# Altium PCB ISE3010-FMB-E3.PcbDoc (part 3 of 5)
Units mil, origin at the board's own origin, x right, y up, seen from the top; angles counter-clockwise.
Board outline 7874.02 x 2362.2 mil, 4 copper layers (Top Layer, MidLayer1, MidLayer2, Bottom Layer), stack 55.6 mil thick; 507 components, 331 nets, 1707 pads, 610 vias.
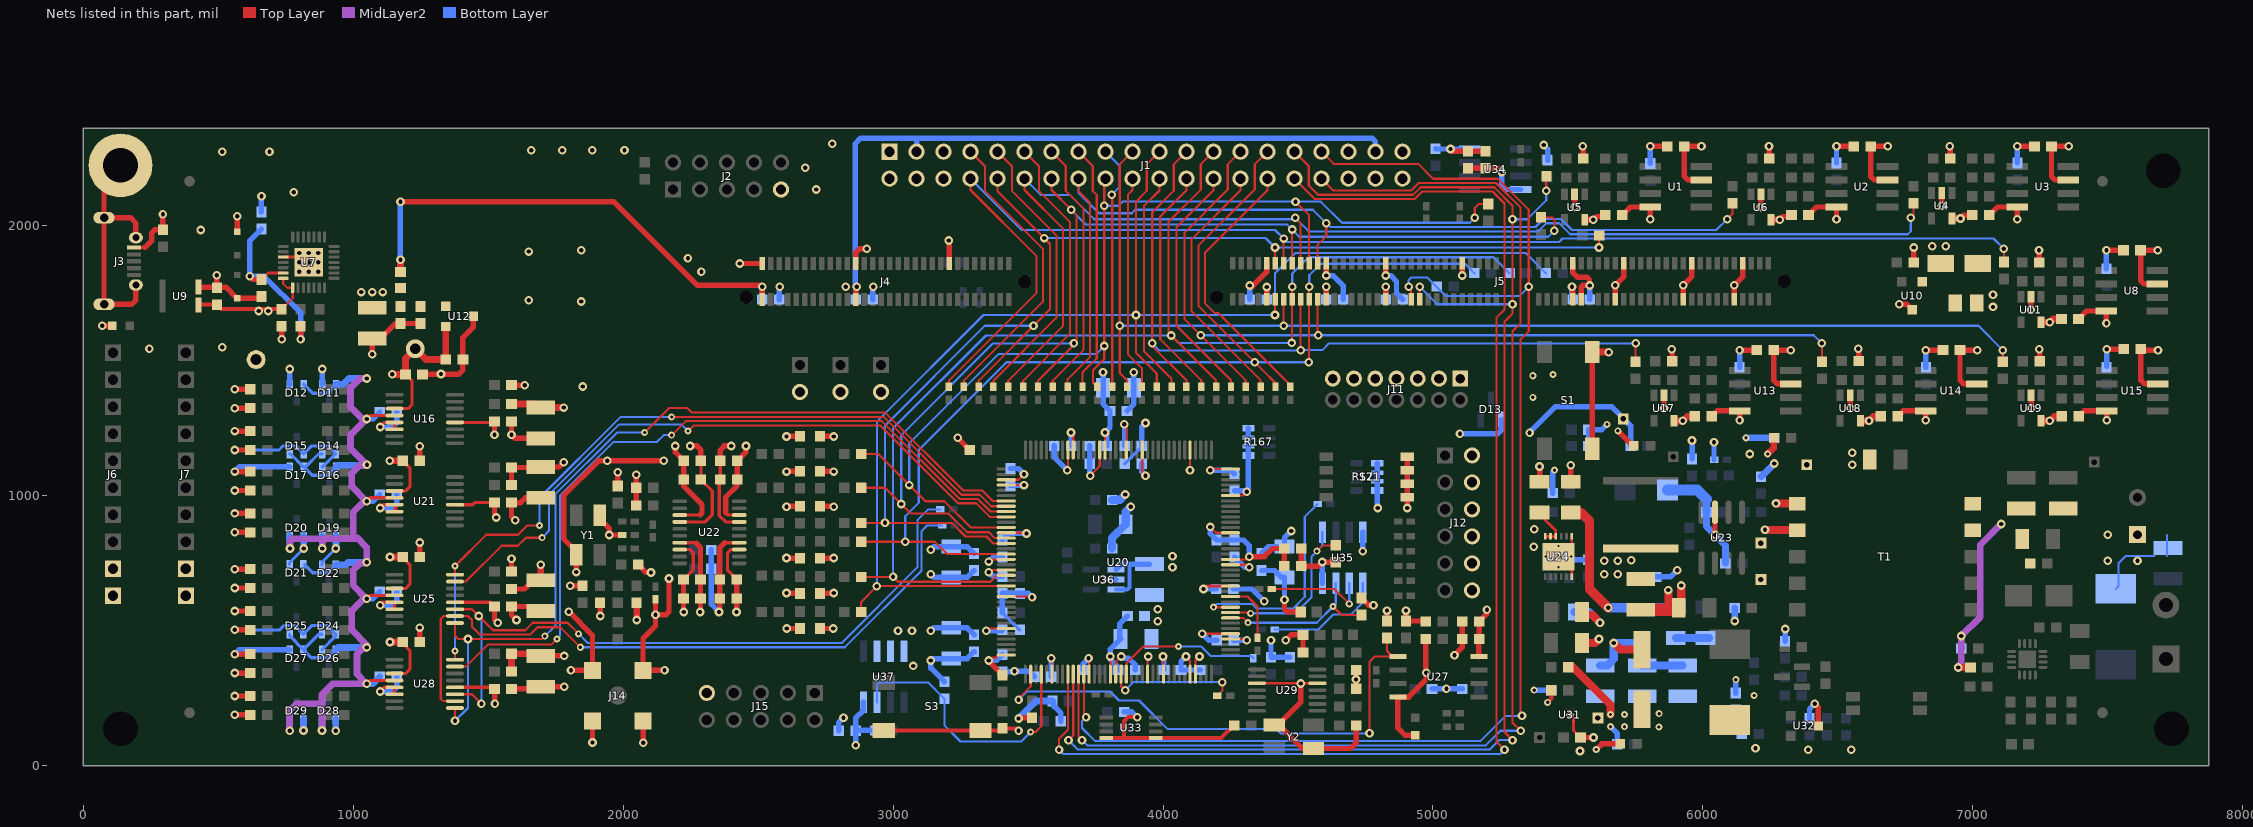
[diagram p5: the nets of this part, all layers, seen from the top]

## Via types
v1: diameter 32, hole 16, Top Layer to Bottom Layer, tented both sides, 495 vias
v2: diameter 26, hole 12, Top Layer to Bottom Layer, tented both sides, 104 vias
v3: diameter 20, hole 8, Top Layer to Bottom Layer, tented both sides, 10 vias
v4: diameter 30, hole 16, Top Layer to Bottom Layer, tented both sides, 1 vias

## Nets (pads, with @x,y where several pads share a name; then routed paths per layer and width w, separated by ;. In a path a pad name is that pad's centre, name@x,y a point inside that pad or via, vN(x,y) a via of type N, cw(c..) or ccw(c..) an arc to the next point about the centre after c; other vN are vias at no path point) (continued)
+3.3V_DVDD: C1.2 C2.2 C3.2 C4.1 C5.1 C9.2 C10.2 C11.2 C12.1 C13.2 C18.1 C23.2 C24.2 C25.2 C26.2 C33.1 C35.2 C36.2 C37.2 C38.2 C43.1 C45.1 C46.1 C53.1 C54.1 C58.2 C63.1 C66.1 C70.1 C71.1 C72.1 C73.1 C76.1 C77.1 C80.2 C83.2 C88.2 C93.1 C100.2 C123.1 C124.1 C126.2 C128.2 C129.2 C131.2 C133.2 C134.2 C140.2 C141.2 C143.1 C144.1 C147.1 C148.1 C149.1 C152.2 C153.1 C154.2 C157.2 C159.1 C160.1 C161.1 C162.1 C163.2 C165.2 C169.2 C170.2 C173.2 C178.1 D13.1 FB2.1 FB5.1 J1.1 J1.39 L1.2 R72.2 R76.2 R78.2 R80.2 R82.2 R84.2 R86.2 R88.2 R90.2 R101.1 R103.2 R111.1 R115.2 R118.2 R121.2 R125.1 R127.1 R128.1 R129.2 R137.2 R142.2 R144.2 R148.2 R156.2 R157.2 R158.2 R167.1 R167.3 R167.5 R167.7 R168.2 R172.2 R187.2 R188.2 R194.2 R195.1 R196.2 R197.2 R201.2 R203.2 R207.1 R208.1 S1.3 S1.4 S2.5 S2.6 S2.7 S2.8 TP8.1 U1.7 U2.7 U3.7 U4.5 U5.5 U6.5 U8.7 U10.1 U11.5 U13.7 U14.7 U15.7 U16.12 U17.5 U18.5 U19.5 U20.4 U20.18 U20.20 U20.31 U20.36 U20.42 U20.53 U20.63 U20.69 U20.76 U20.86 U20.90 U20.103 U20.122 U20.125 U20.129 U20.135 U21.12 U22.3 U22.7 U22.14 U22.18 U25.12 U27.8 U28.12 U34.8 U35.8 U36.1 U36.3 U37.8 | length 13036.1
  Top Layer w8: U25.12@1376.7,604.04 1419.04,604.04 ; v1(3345,500) 3334.94,500 3334.28,500.66 3341.22,507.61 3341.22,508.78 U20.31@3419.29,508.78 ; v1@3355,386.5 3368.5,400 3380,400 3390.35,410.35 U20.36@3419.29,410.35 ; v1@3360.06,717.2 3360.06,723.56 3361.81,725.31 U20.20@3419.29,725.31 ; v1@3360.06,756.57 3360.06,762.93 3361.81,764.68 U20.18@3419.29,764.68 ; U20.4@3419.29,1040.28 3479.72,1040.28 3480,1040 v1(3485,1040) ; v1@3585,400 v1(3586.5,398.5) 3588.58,396.42 U20.42@3588.58,339.49 ; v1@3659.21,1229.43 3665.57,1229.43 3667.32,1227.68 U20.135@3667.32,1170.2 ; v1(3785,1235) 3785.43,1234.57 U20.129@3785.43,1170.2 ; v1(3805,405) 3810,405 3805.12,400.12 U20.53@3805.12,339.49 ; v1(3856.06,1264.92) 3864.17,1256.8 U20.125@3864.17,1170.2 ; U20.122@3923.23,1170.2 3923.23,1086.77 v1(3935,1075) ; v1(4000,405) 4001.97,403.03 U20.63@4001.97,339.49 ; U20.69@4120.08,339.49 4120.08,390.08 v1(4135,405) ; U20.76@4250,469.41 4305.59,469.41 v1(4310,465) ; U20.90@4250,745 4310,745 v1(4320,735) ; U20.103@4250,1000.91 4295.91,1000.91 v1(4310,1015)
  Top Layer w10: v1(4150,655) 4161.26,666.26 U20.86@4250,666.26
  Top Layer w12: U28.12@1377.2,290.75 1517.76,290.75 C100.2@1523.5,285 ; U25.12@1377.2,605.75 1507.76,605.75 C80.2@1523.5,590 ; U21.12@1377.2,967.2 1442.2,967.2 1450,975 C58.2@1523.5,975 ; U16.12@1377.2,1272.2 1520.71,1272.2 C38.2@1523.5,1275 ; U22.7@2209.76,826.61 2268.39,826.61 2270,825 ; U22.3@2209.76,928.98 2283.98,928.98 2285,930 ; 2376.61,826.61 U22.14@2430.24,826.61 ; 2380,936.93 2387.95,928.98 U22.18@2430.24,928.98
  Top Layer w20: C80.2@1523.5,590 1523.5,541.5 v1(1535,530) ; C58.2@1523.5,975 1523.5,926.5 v1(1530,920) ; v1(1523.5,1226.5) C38.2@1523.5,1275 ; v1(1525,230) 1525,263.5 ; R118.2@1586.5,655 1635,655 1667.09,687.09 C71.1@1695,687.09 ; R84.2@1586.5,1040 R80.2@1586.5,1105 C46.1@1695,1105 ; C93.1@1695,407.09 v1(1782.09,407.09) ; C46.1@1695,1107.09 1762.09,1107.09 v1(1780,1125) ; R88.2@2048.5,965 R86.2@2048.5,1030 v1(2048.5,1078.5) ; v1(2192.99,1185) 2192.99,1162.01 C43.1@2225,1130 C53.1@2225,1060 2225,1035 2292,968 2292,937 2285,930 ; 2270,825 2286.5,808.5 C73.1@2286.5,690 C77.1@2286.5,620 2286.5,571.5 v1(2285,570) ; v1(2355,570) 2358.5,573.5 C76.1@2358.5,620 C72.1@2358.5,690 2358.5,808.5 2376.61,826.61 ; 2380,936.93 2380,994.92 2421.5,1036.42 ; C54.1@2422.99,1046.42 C54.1@2422.99,1060 C45.1@2422.99,1120 ; C45.1@2422.99,1130 2455,1162.01 v1(2455,1185) ; R125.1@2730,508.51 v1(2778.51,508.51) ; R111.1@2730,638.51 2778.51,638.51 v1(2780,640) ; R101.1@2730,768.51 2778.51,768.51 v1(2780,770) ; R90.2@2730,961.5 2778.5,961.5 v1(2780,960) ; R82.2@2730,1091.5 2778.5,1091.5 v1(2780,1090) ; R76.2@2730,1221.5 2778.5,1221.5 v1(2780,1220) ; v1@3240,1213.5 R78.2@3283.5,1170 ; v1(3355,390) 3355,386.5 R144.2@3405,336.5 ; v1(3465,175) 3468.5,178.5 R148.2@3515,178.5 ; v1(4450,615) 4450,580 4460,570 FB2.1@4510.47,570 ; C63.1@4511.5,805 C66.1@4511.5,740 4575,740 v1(4590,755) 4591.5,753.5 R103.2@4640,753.5 ; R121.2@4735,621.5 4735.57,621.5 4762.06,595 v1(4780,595) ; R127.1@4830,536.5 v1(4830,575) ; v1@4900,580 v1(4900,575) R128.1@4900,536.5 4972.01,536.5 R129.2@4973.5,535 ; v1(4905,955) S2.5@4905,995 S2.6@4905,1045 S2.7@4905,1095 S2.8@4905,1145 ; v1(5065,2285) 5073.5,2276.5 C4.1@5130,2276.5 C5.1@5195,2276.5 ; U27.8@5170,404.68 5170,468.5 C88.2@5171.5,470 C83.2@5171.5,535 5200,563.5 v1(5200,578) ; S1.3@5590,1175 S1.4@5590,1533.27 ; v1(5594.41,2022.76) 5606.65,2035 C9.2@5638.5,2035 ; U1.7@5994,2170 5945,2170 5931.5,2183.5 C1.2@5931.5,2295 v1(5995,2295) ; v1(6284.41,2022.76) 6296.65,2035 C10.2@6328.5,2035 ; U13.7@6325,1415 6276,1415 6262.5,1428.5 C25.2@6262.5,1540 v1(6326,1540) ; U2.7@6684,2170 6635,2170 6621.5,2183.5 C2.2@6621.5,2295 v1(6685,2295) ; v1(6954.41,2027.76) 6966.65,2040 C11.2@6998.5,2040 ; U14.7@7015,1415 6966,1415 6952.5,1428.5 C26.2@6952.5,1540 v1(7016,1540) ; U3.7@7354,2170 7305,2170 7291.5,2183.5 C3.2@7291.5,2295 v1(7355,2295) ; U8.7@7684,1785 7635,1785 7621.5,1798.5 C13.2@7621.5,1910 v1(7685,1910) ; U15.7@7685,1415 7636,1415 7622.5,1428.5 7622.5,1540 v1(7686,1540)
  Top Layer w25: R142.2@1586.5,350 R137.2@1586.5,415 1687.09,415 C93.1@1695,407.09 ; R72.2@1586.5,1340 1682.09,1340 C33.1@1695,1327.09 v1(1780,1327.09) ; C71.1@1695,687.09 v1(1695,745) ; v1(2050,540) R115.2@2050,603.5 ; U5.5@5562.4,2022.76 v1(5594.41,2022.76) ; S1.4@5590,1533.27 v1@5651.73,1533.27 ; U17.5@5893.4,1277.76 v1(5925.41,1277.76) 5942.49,1294.84 C35.2@5969.5,1294.84 ; U6.5@6252.4,2022.76 v1(6284.41,2022.76) ; U18.5@6583.4,1277.76 v1(6615.41,1277.76) 6632.49,1294.84 C36.2@6659.5,1294.84 ; U4.5@6922.4,2027.76 v1(6954.41,2027.76) ; U11.5@7252.72,1642.76 v1(7284.72,1642.76) 7296.97,1655 C23.2@7328.82,1655 ; U19.5@7253.4,1277.76 v1(7285.41,1277.76) 7302.49,1294.84 C37.2@7329.5,1294.84
  Bottom Layer w8: v1(3345,500) 3334.94,500 3334.28,500.66 3337.12,503.5 C157.2@3405,503.5
  Bottom Layer w15: U36.3@3826,652.6 3867.6,652.6 3876.03,661.03 3876.03,747.09
  Bottom Layer w20: R158.2@660,2051.5 v1(660,2110) ; R207.1@2326.5,800 R208.1@2326.5,730 2326.5,598.5 v1(2355,570) ; v1(2861.5,76.5) C178.1@2861.5,130 ; U37.8@2890,235 2890,205 2861.5,176.5 C178.1@2861.5,130 ; R203.2@2934.37,131.42 2862.91,131.42 C178.1@2861.5,130 ; v1(3140,710) 3152.09,697.91 C144.1@3215,697.91 3274.41,697.91 C148.1@3300,723.5 ; R194.2@3190,311.5 3140,361.5 v1(3140,390) 3147.11,397.11 C160.1@3215,397.11 3274.41,397.11 C162.1@3300,422.7 ; v1(3345,500) 3401.5,500 C157.2@3405,503.5 ; v1(3354.49,717.2) 3370.19,701.5 C152.2@3405,701.5 ; v1(3354.49,756.57) 3371.42,773.5 C140.2@3405,773.5 ; v1(3355,390) 3383.5,390 C165.2@3405,411.5 ; C133.2@3434.65,1038.35 3483.35,1038.35 v1(3485,1040) ; C173.2@3586.5,330 v1(3586.5,398.5) ; FB5.1@3590.47,240 3595.99,234.48 3595.99,221.01 3621.5,195.5 R201.2@3621.5,165 ; v1(3659.21,1235) 3659.45,1234.76 C129.2@3659.45,1185 ; v1(3777.91,1457.91) C123.1@3777.91,1400 3777.91,1340.59 C124.1@3803.5,1315 3803.5,1253.5 v1(3785,1235) 3791.5,1228.5 C128.2@3791.5,1185 ; U36.1@3826,727.4 3845.68,747.09 3876.03,747.09 C149.1@3950,747.09 ; C170.2@3833.5,355 3833.5,365.5 3805,394 v1(3805,405) 3805,432.09 C161.1@3842.91,470 ; C161.1@3840,472.91 3840,526.5 C159.1@3868.5,555 ; v1(3856.06,1264.92) 3858.5,1262.47 C126.2@3858.5,1185 ; C131.2@3921.5,1119.02 3921.5,1088.5 v1(3935,1075) ; v1(4000,405) 4003.5,401.5 C169.2@4003.5,355 ; v1(4150,655) C154.2@4196.85,655 ; C163.2@4261.5,465 v1(4310,465) ; C141.2@4265,773.5 4303.5,735 v1(4320,735) ; C134.2@4265,1018.5 4306.5,1018.5 v1(4310,1015) 4316.5,1021.5 R167.7@4316.5,1149.5 R167.5@4316.5,1184.5 R167.3@4316.5,1215.5 R167.1@4316.5,1250.5 ; C147.1@4365,723.5 4413.5,723.5 4439.09,697.91 C143.1@4450,697.91 v1(4450,615) ; v1(4400,465) R188.2@4400,401.5 R187.2@4470,401.5 ; U35.8@4590,676 v1(4590,755) ; v1(4900,575) v1@4900,580 ; R196.2@4996.5,285 v1(5050,285) R195.1@5108.5,285 ; R156.2@5010,2286.5 5011.5,2285 v1(5065,2285) U34.8@5136,2285 ; v1(5100,1230) 5239.8,1230 5252.4,1242.6 D13.1@5252.4,1282.6 ; v2(5375,280) R197.2@5438.5,280 ; v1(5410,2300) 5425,2285 R157.2@5425,2243.11
  Bottom Layer w25: v1(3465,175) 3530,240 FB5.1@3590.47,240 ; v2(6160,1215) R168.2@6265,1215 ; R172.2@6215,1071.5 6216.5,1071.5 v1(6265,1120)
  other v1: 5635,710 5685,710 4035,736 5635,760 5685,760 5735,761 4035,776 3240,1215 5651.73,1532.27 6850,1925 6900,1925
+3V3_USB: C15.1 R29.2 R158.1 U7.6 | length 723.9
  Top Layer w10: C15.1@660,1801.5 684.1,1825.6 U7.6@741,1825.6
  Top Layer w20: v1(616.5,1813.5) 628.5,1801.5 C15.1@660,1801.5 ; v1(805,1580) R29.2@805,1628.5
  Bottom Layer w20: R158.1@660,1988.5 616.5,1945 v1(616.5,1813.5) 670.04,1813.5 805,1678.54 v1(805,1580)
+4.096VREF: C27.1 C28.2 C44.2 C64.2 C89.2 TP1.1 U12.2 U16.3 U21.3 U25.3 U28.3 | length 1262.2
  Top Layer w12: U28.3@1152.8,341.93 1195,341.93 1210,356.93 1210,427.05 C89.2@1183.5,453.54 ; U25.3@1152.8,656.93 1195,656.93 1210,671.93 1210,745 C64.2@1181.46,773.54 ; U21.3@1152.8,1018.39 1195,1018.39 1210,1033.39 1210,1103.5 C44.2@1183.5,1130 ; U16.3@1152.8,1323.39 1203.39,1323.39 1217.76,1337.76 1217.76,1425.75 C28.2@1193.5,1450
  Top Layer w25: v1(1135,1130) C44.2@1183.5,1130 ; v1(1136.46,458.54) C89.2@1181.46,458.54 ; v1(1136.46,773.54) C64.2@1181.46,773.54 ; v1(1145,1450) C28.2@1193.5,1450 1193.5,1508.5 TP1.1@1230,1545 1270,1505 C27.1@1343.5,1505 1342.5,1506 U12.2@1342.5,1627.5
+5V_AVDD: C19.1 C20.1 C21.2 C125.2 C136.2 C155.2 C172.2 D11.2 D12.2 D14.2 D15.2 D16.2 D17.2 D19.2 D20.2 D21.2 D22.2 D24.2 D25.2 D26.2 D27.2 D28.2 D29.2 FB1.2 TP2.1 U12.1 U16.4 U21.4 U25.4 U28.4 | length 4574.2
  Top Layer w12: v1(1050,303.54) 1062.8,316.34 U28.4@1152.8,316.34 ; v1(1050,618.54) 1062.8,631.34 U25.4@1152.8,631.34 ; v1(1050,979.9) 1062.9,992.8 U21.4@1152.8,992.8 ; v1(1050,1284.9) 1062.9,1297.8 U16.4@1152.8,1297.8 ; U28.4@1152.8,314.74 U28.4@1157.7,314.74
  Top Layer w25: v1(884.41,130.59) v1@885,130
  MidLayer2 w25: v1(764.41,130) 764.41,204.41 790,230 884.41,230 ; v1(765.71,805) 765.71,831.97 775.04,841.3 885.71,841.3 ; v1(884.41,130.59) 884.41,230 ; v1(885.71,805) 885.71,841.3 ; 1013.7,845.3 1050,809 v1(1050,753.54) 1046.4,749.94 1024.94,749.94 1000,725 1000,668.54 v1(1050,618.54) 1038.54,618.54 995,575 995,502.64 1050,447.64 v1(1050,438.54) 1046.4,434.94 1034.96,434.94 1013.7,413.68 1013.7,339.84 v1(1050,303.54) 923.54,303.54 884.41,264.41 884.41,230 ; v1(1050,1435) 1025,1435 990,1400 990,1330 1035.1,1284.9 v1(1050,1284.9) 990,1224.9 990,1175.99 v1(1051.19,1114.8) 1047.69,1111.3 1021.3,1111.3 995,1085 995,1034.9 v1(1050,979.9) 1039.9,979.9 1000,940 1000,851 1009.7,841.3 885.71,841.3
  Bottom Layer w12: D25.2@764.41,487.05 764.41,481.22 D27.2@815.59,430.04 ; D15.2@765.12,1155.08 767.92,1155.08 814.93,1108.07 D17.2@816.3,1108.07 ; D12.2@816.3,1413.07 849.37,1380 903.23,1380 D11.2@936.3,1413.07 ; D21.2@820.59,745.04 850.14,715.49 906.49,715.49 935.59,744.59 D22.2@935.59,745.04 ; D24.2@884.41,487.05 872.6,487.05 D27.2@815.59,430.04 ; D14.2@885.12,1155.08 871.46,1155.08 824.45,1108.07 D17.2@816.3,1108.07 ; D26.2@935.59,430.04 906.04,400.49 845.14,400.49 D27.2@815.59,430.04 ; D16.2@936.3,1108.07 904.8,1076.57 847.79,1076.57 D17.2@816.3,1108.07
  Bottom Layer w20: v1(1050,618.54) 1072.05,618.54 C155.2@1098.5,645 ; v1(1050,979.9) 1073.4,979.9 C136.2@1098.5,1005 ; v1@1050,1114.9 1050.1,1114.8 v1(1051.19,1114.8) ; v1(1050,1284.9) 1050.1,1285 1073.5,1285 C125.2@1098.5,1310
  Bottom Layer w25: v1(764.41,130) D29.2@764.41,172.05 ; v1@765.12,805 D20.2@765.12,850.08 ; v1(884.41,130.59) D28.2@884.41,172.05 ; v1@885.12,805 D19.2@885.12,850.08 ; D26.2@935.59,430.04 944.09,438.54 v1(1050,438.54) ; D22.2@935.59,745.04 971.5,745.04 980,753.54 v1(1050,753.54) ; D16.2@936.3,1108.07 941.2,1112.97 1049.36,1112.97 v1(1051.19,1114.8) ; D11.2@936.3,1413.07 962.2,1413.07 984.13,1435 v1(1050,1435) ; v1(1050,303.54) 1072.05,303.54 C172.2@1098.5,330
  other v1: 1030,1755 1070,1755 1110,1755
+5V_CNTL: C51.1 C52.1 C114.2 C115.2 C116.2 C117.2 C118.2 C119.2 FB1.1 J1.3 J1.37 J4.158 J4.180 J5.48 J5.84 J5.98 J5.112 R169.2 R183.1 TP3.1 U24.10 U24.11 U24.12 | length 6252.9
  Top Layer w10: C51.1@5395,937.91 5395,931 5455.16,870.84 U24.10@5455.16,849.8 U24.11@5435.47,849.8 U24.12@5415.79,849.8
  Top Layer w20: v1(1175,2090) 1965,2090 2275,1780 2510,1780 v1(2515.49,1774.51) J4.180@2515.49,1727.07 ; J4.158@2861.94,1727.07 2861.94,1771.94 v1(2865,1775) ; J5.112@4383.86,1728.07 v1(4383.86,1773.86) ; J5.98@4604.33,1728.07 v1(4604.33,1774.33) ; J5.84@4824.8,1728.07 4824.8,1774.8 v1(4825,1775) ; C52.1@5510,937.91 5549.09,937.91 ; v1(5515,1775) 5517.72,1772.28 J5.48@5517.72,1728.07
  Top Layer w25: FB1.1@1175,1829.53 v1(1175,1875)
  Top Layer w35: 5549.09,937.91 5580,907 5580,655 v1(5650,585)
  Bottom Layer w20: v1(1175,1875) v1(1175,2090) ; C119.2@2515.49,1727.07 v1(2515.49,1774.51) ; C118.2@2861.94,1727.07 2861.94,1773.06 2860,1775 2860,2305 2880,2325 3087.01,2325 ; J1.3@3087.01,2275 3087.01,2325 ; C117.2@4383.86,1728.07 v1(4383.86,1773.86) ; C116.2@4604.33,1728.07 v1(4604.33,1774.33) ; J1.37@4787.01,2275 4787.01,2312.99 4775,2325 3087.01,2325 ; C115.2@4824.8,1728.07 4824.8,1774.8 v1(4825,1775) ; v1@5358,1235 5453,1330 5663,1330 5733.5,1259.5 5733.5,1256.5 ; v1(5515,1775) 5515,1730.79 C114.2@5517.72,1728.07 ; TP3.1@5705,1285 5733.5,1256.5 ; R169.2@5733.5,1185 5733.5,1256.5
  Bottom Layer w35: v1(5650,585) 5897.91,585 R183.1@5900,587.09
  other v1: 5372.97,811 5375,876 5358,1234 2825,1775
+5V_USB: C17.1 C22.1 U7.7 U7.8 U9.3 | length 473.4
  Top Layer w8: C22.1@735,1691.5 775.9,1732.4 U7.8@775.9,1771 756,1771 741,1786 U7.7@741,1805.9
  Top Layer w15: U9.3@426.93,1706.54 428.9,1708.5 C17.1@495,1708.5 512.01,1691.5 C22.1@735,1691.5
  other v1: 650,1685 685,1685
"+6.0 VDD": C91.1 C166.1 C167.1 C168.1 C174.1 D7.1 R139.2 R182.1 R183.2 R204.2 R206.2 TP9.1 | length 447.7
  Top Layer w30: R139.2@5501.5,365 5519,365 5658,226 v2(5658,190)
  Bottom Layer w20: v2(5658,145) 5683.5,119.5 R206.2@5683.5,80
  Bottom Layer w30: R183.2@5900,472.91 R182.1@6010,472.91 R182.1@6022.09,472.91
  other v2: 5837,144 5710,145 5710,190 5838,193
+24VDC_FIL: C48.1 C49.1 C50.1 C67.1 C146.1 D23.1 R98.2 R140.2 R186.2 T1.1 T1.2 | length 1020.1
  Top Layer w8: R98.2@7180,827.91 R98.2@7182.91,825
  Top Layer w25: v1(6946,364) R140.2@6991.5,364
  MidLayer2 w25: v1(6946,364) 6942,364 6957,379 v1(6957,481.01) 7028,552.01 7028,819 v1(7105,896)
  Bottom Layer w8: D23.1@7530,655.49 7540,665.49 7540,750 7567.09,777.09 7672.91,777.09 ; 7720,777.09 7720,855
  Bottom Layer w25: v1(6957,481.01) 6957.5,480.5 R186.2@6957.5,435
  other v1: 7500,760 7610,760 7500,856.1
CLKN_CH_U: J1.9 R47.1 | length 1058.3
  Top Layer w8: R47.1@3371.81,1403.62 3371.81,1426.81 3605,1660 3605,1965 3440,2130 3440,2222.01 J1.9@3387.01,2275
CLKN_CH_V: J1.13 R51.1 | length 967.1
  Top Layer w8: J1.13@3587.01,2275 3640,2222.01 3640,2130 3705,2065 3705,1540 3591.81,1426.81 R51.1@3591.81,1403.62
CLKN_CH_W: J1.17 R55.1 | length 922.9
  Top Layer w8: J1.17@3787.01,2258.6 J1.17@3787.01,2275 ; v1(3810,2115) 3811.81,2113.19 R55.1@3811.81,1403.62
  Bottom Layer w8: J1.17@3787.01,2275 3840,2222.01 3840,2145 v1(3810,2115)
CLKN_U_PH: J1.22 R59.1 | length 837.2
  Top Layer w8: J1.22@3987.01,2175 3987.01,2131.51 3930,2074.5 3930,1535 4031.81,1433.19 R59.1@4031.81,1403.62
CLKN_V_PH: J1.26 R63.1 | length 911.7
  Top Layer w8: J1.26@4187.01,2175 4187.01,2132.01 4050,1995 4050,1629.81 4251.81,1428 R63.1@4251.81,1403.62
CLKN_VDC: J1.34 U20.47 | length 4673.4
  Top Layer w8: U20.47@3687.01,339.49 3687.01,107.99 v1(3700,95) ; J1.34@4587.01,2175 4630.61,2131.4 4920,2131.4 4947.8,2159.2 5233.46,2159.2 5325,2067.66 5325,1640 5295,1610 5295,160 v1(5325,130)
  Bottom Layer w8: v1(3700,95) 3719.4,75.6 5195.6,75.6 5250,130 v1(5325,130)
CLKN_W_PH: J1.30 R67.1 | length 1006.7
  Top Layer w8: J1.30@4387.01,2175 4387.01,2132.01 4155,1900 4155,1714 4192,1677 4205.72,1677 4471.81,1410.91 R67.1@4471.81,1403.62
CLKP_CH_U: C60.1 J1.10 J5.109 R23.1 R46.1 U20.15 | length 4752
  Top Layer w8: C60.1@2881.5,900 v1(2970,900) 3217.66,900 3268.46,849.2 3345.87,849.2 3371.33,823.74 U20.15@3419.29,823.74 ; R46.1@3316.81,1403.62 3316.81,1426.81 3581.59,1691.59 3581.59,1933.41 v1(3560,1955) 3387.01,2127.99 J1.10@3387.01,2175 ; v1(4415,1920) 4415.35,1919.65 J5.109@4415.35,1861.93 ; v1(5615,1920) R23.1@5615,1950
  Bottom Layer w8: v1(2970,900) 2970,1260 3340,1630 v1(3520,1630) ; v1(3560,1955) 4380,1955 v1(4415,1920) v1(5615,1920)
CLKP_CH_V: C56.1 J1.14 J5.105 R21.1 R50.1 U20.14 | length 4580.9
  Top Layer w8: C56.1@2881.5,1030 2970,1030 v1(3030,970) 3065,935 3205,935 3275,865 3355.07,865 3376.64,843.42 U20.14@3419.29,843.42 ; R50.1@3536.81,1403.62 3536.81,1426.81 3680,1570 3680,2040 v1(3660,2060) 3587.01,2132.99 J1.14@3587.01,2175 ; J5.105@4478.35,1861.93 v1(4478.35,1986.65) ; R21.1@5400,2031.5 5443.5,2031.5 5450,2025 v1(5450,1982.36)
  Bottom Layer w8: v1(3030,970) 3030,1225 3370,1565 v1(3670,1565) ; v1(3660,2060) 3715,2005 4460,2005 v1(4478.35,1986.65) 4505,1960 5427.64,1960 v1(5450,1982.36)
CLKP_CH_W: C42.1 J1.18 J5.101 R18.1 R54.1 U20.12 | length 4235.2
  Top Layer w8: C42.1@2881.5,1155 2945,1155 v1(3060,1040) 3120,980 3190,980 3287.21,882.79 U20.12@3419.29,882.79 ; R54.1@3756.81,1403.62 3740.43,1420 3740.43,1465.43 3782.2,1507.2 v1(3782.2,1555) v1(3782.2,2075) 3782.2,2170.19 J1.18@3787.01,2175 ; v1(4490.67,2090) 4541.34,2039.33 J5.101@4541.34,1861.93 ; v1(5155,2030) 5155,2066.5 5170,2081.5 R18.1@5205,2081.5
  Bottom Layer w8: v1(3060,1040) 3060,1195 3390,1525 3752.2,1525 v1(3782.2,1555) ; v1(3782.2,2075) 3836.1,2075 3851.1,2090 v1(4490.67,2090) 4585,2090 4663.4,2011.6 5136.6,2011.6 v1(5155,2030)
CLKP_U_PH: C82.1 J1.21 J5.110 R58.1 R160.2 U20.23 | length 5065.7
  Top Layer w8: C82.1@2881.5,570 2881.5,606.5 v1(2940,665) 2941.26,666.26 U20.23@3419.29,666.26 ; R58.1@3976.81,1403.62 3976.81,1453.19 3900,1530 v1(3900,1670) 3900,2090 3940,2130 3940,2227.99 J1.21@3987.01,2275 ; v1(4415,1670) 4415.35,1670.35 J5.110@4415.35,1728.07
  Bottom Layer w8: v1(2940,665) 2940,1275 3335,1670 v1(3900,1670) v1(4415,1670) 4415.34,1670.34 4415.34,1825.34 4490,1900 5343.5,1900 R160.2@5418.5,1825
CLKP_V_PH: C69.1 J1.25 J5.106 R62.1 R161.2 U20.21 | length 4862.7
  Top Layer w8: C69.1@2881.5,700 v1(3000,700) 3017.94,682.06 3360.84,682.06 3384.41,705.63 U20.21@3419.29,705.63 ; J1.25@4187.01,2275 4140,2227.99 4140,2134.5 4020,2014.5 4020,1604.21 v1(4030,1594.21) 4059.21,1565 4196.81,1427.4 R62.1@4196.81,1403.62 ; v1(4476.65,1566.65) 4478.35,1566.65 J5.106@4478.35,1728.07 4478.35,1774.29 v1(4479.05,1775)
  Bottom Layer w8: v1(3000,700) 3000,1250 3344.21,1594.21 v1(4030,1594.21) 4057.56,1566.65 v1(4476.65,1566.65) ; v1(4479.05,1775) 4479.05,1824.05 4539.2,1884.2 5224.3,1884.2 R161.2@5283.5,1825
CLKP_VDC: J1.33 J5.78 R163.2 U20.48 | length 5212.3
  Top Layer w8: U20.48@3706.69,339.49 3706.69,188.31 v1(3715,180) ; J1.33@4587.01,2275 4632.01,2230 4945,2230 5000,2175 5240,2175 5355,2060 v1(5355,1775) 5355,1610 5325,1580 5325,190 v1(5330,185) ; v1(4910,1775) 4919.29,1765.71 J5.78@4919.29,1728.07
  Bottom Layer w8: v1(3715,180) 3700,165 3700,140 3748.6,91.4 5175.6,91.4 5269.2,185 v1(5330,185) ; v1(4910,1775) 4910,1800 4919.2,1809.2 4979.3,1809.2 R163.2@5013.5,1775 5048.5,1740 5320,1740 v1(5355,1775)
CLKP_W_PH: C62.1 J1.29 J5.102 R66.1 R162.2 U20.17 | length 4559.4
  Top Layer w8: C62.1@2881.5,830 v1(3045,830) 3155,830 3200.63,784.37 U20.17@3419.29,784.37 ; J1.29@4387.01,2275 4340,2227.99 4340,2135 4131,1926 4131,1704 v1(4340,1495) 4370,1465 4416.81,1418.19 R66.1@4416.81,1403.62 ; v1(4540,1495) 4541.34,1496.34 J5.102@4541.34,1728.07 4541.34,1774.29 v1(4542.05,1775)
  Bottom Layer w8: v1(3045,830) 3045,925 3095,975 3095,1169.84 3420.16,1495 v1(4340,1495) v1(4540,1495) ; v1(4542.05,1775) 4542.05,1817.05 4585,1860 5118.5,1860 R162.2@5153.5,1825
CLOCK_Y1: R147.2 U20.55 | length 496.1
  Top Layer w8: U20.55@3844.49,339.49 3844.49,295.51 v1(3860,280) ; R147.2@4201.38,260 4220,278.62 v1(4220,310)
  Bottom Layer w8: v1(3860,280) 3890,310 v1(4220,310)
CLOCK_Y2: R189.2 U20.56 | length 554.5
  Top Layer w8: U20.56@3864.17,339.49 3864.17,379.17 3927,442 v2(4057,442)
  Bottom Layer w8: v2(4057,442) 4142,442 4177,407 4326.62,407 R189.2@4335,398.62
CLOCK_Y3: R133.2 U20.84 | length 231.7
  Top Layer w8: U20.84@4250,626.89 4313.11,626.89 4350,590 R133.2@4350,473.62
DGND: C1.1 C2.1 C3.1 C4.2 C5.2 C9.1 C10.1 C11.1 C12.2 C13.1 C14.2 C15.2 C17.2 C18.2 C19.2 C20.2 C21.1 C22.2 C23.1 C24.1 C25.1 C26.1 C27.2 C28.1 C32.1 C33.2 C34.1 C35.1 C36.1 C37.1 C38.1 C39.1 C40.1 C41.2 C43.2 C44.1 C45.2 C46.2 C47.1 C51.2 C52.2 C53.2 C54.2 C55.2 C57.1 C58.1 C59.1 C61.1 C63.2 C64.1 C65.2 C66.2 C68.1 C70.2 C71.2 C72.2 C73.2 C75.1 C76.2 C77.2 C78.2 C79.2 C80.1 C81.1 C83.1 C85.1 C86.1 C87.2 C88.1 C89.1 C91.2 C92.1 C93.2 C94.1 C96.1 C97.1 C99.1 C100.1 C101.2 C102.1 C104.1 C105.1 C106.2 C107.2 C108.2 C110.1 C111.1 C112.1 C113.1 C114.1 C115.1 C116.1 C117.1 C118.1 C119.1 C120.1 C121.1 C122.1 C123.2 C124.2 C125.1 C126.1 C127.1 C128.1 C129.1 C130.2 C131.1 C132.1 C133.1 C134.1 C136.1 C137.2 C138.2 C140.1 C141.1 C142.1 C143.2 C144.2 C145.2 C147.2 C148.2 C149.2 C150.2 C151.1 C152.1 C153.2 C154.1 C155.1 C156.2 C157.1 C158.1 C159.2 C160.2 C161.2 C162.2 C163.1 C164.2 C165.1 C166.2 C167.2 C168.2 C169.1 C170.1 C171.1 C172.1 C173.1 C174.2 C175.1 C178.2 D1.1 D2.1 D3.1 D4.2 D5.2 D9.1 D10.2 D11.1 D12.1 D14.1 D15.1 D16.1 D17.1 D18.2 D19.1 D20.1 D21.1 D22.1 D24.1 D25.1 D26.1 D27.1 D28.1 D29.1 J1.2 J1.4 J1.5 J1.6 J1.35 J1.36 J1.38 J1.40 J2.9 J3.5 J4.135 J4.157 J4.179 J5.7 J5.10 J5.19 J5.22 J5.35 J5.38 J5.46 J5.47 J5.65 J5.83 J5.97 J5.111 J6.9 J6.10 J7.9 J7.10 J8.2 J9.2 J10.2 J11.1 J11.3 J11.5 J11.7 J11.9 J11.11 J11.13 J12.2 J12.4 J12.6 J12.8 J12.10 J12.12 J14.2 J15.9 R2.2 R3.2 R4.2 R22.1 R25.2 R31.2 R35.2 R36.2 R43.2 R75.1 R81.1 R89.1 R97.1 R100.2 R108.2 R110.2 R113.1 R114.1 R116.1 R124.2 R134.1 R166.2 R170.1 R171.2 R171.4 R171.6 R171.8 R173.1 R178.1 R180.1 R184.1 R192.1 R200.1 S3.3 S3.4 T1.9 T1.10 TP6.1 TP7.1 U1.4 U2.4 U3.4 U4.2 U5.2 U6.2 U7.3 U7.29 U8.4 U9.2 U10.3 U11.2 U12.3 U13.4 U14.4 U15.4 U16.5 U16.6 U17.2 U18.2 U19.2 U20.3 U20.13 U20.25 U20.49 U20.54 U20.60 U20.68 U20.77 U20.91 U20.96 U20.108 U20.113 U20.130 U20.136 U21.5 U21.6 U22.4 U22.8 U22.13 U22.17 U23.7 U24.6 U24.7 U24.13 U25.5 U25.6 U27.4 U28.5 U28.6 U29.5 U29.10 U31.2 U31.5 U32.3 U33.4 U33.5 U34.4 U35.4 U36.2 U37.2 U37.3 U37.4 Y1.2 Y1.4 Y2.2 Y2.4 | length 24920.7
  Top Layer w8: J14.2@1880,160 J14.2@1886.5,166.5 ; J1.4@3087.01,2175 J1.4@3100,2162.01 ; U20.25@3419.29,626.89 3513.11,626.89 v1(3515,625) ; U20.13@3419.29,863.11 3491.85,863.11 v1(3494.49,860.47) ; U20.3@3419.29,1059.96 3464.37,1059.96 v1(3484.8,1080.39) ; v1(3645,1095) 3647.64,1097.64 U20.136@3647.64,1170.2 ; v1@3722.79,400 v1(3724.29,398.5) 3726.38,396.42 U20.49@3726.38,339.49 ; v1(3730,1075) 3765.75,1110.75 U20.130@3765.75,1170.2 ; U20.54@3824.8,339.49 3824.8,385 3825.24,385 v1(3845.24,405) ; U20.60@3942.91,339.49 3942.91,402.91 v1(3945,405) ; v1(4085,405) 4100.39,389.61 U20.68@4100.39,339.49 ; v1(4100,1095) 4100.39,1095.39 U20.113@4100.39,1170.2 ; v1(4145.91,489.09) U20.77@4250,489.09 ; v1(4175,885) 4196.89,863.11 U20.96@4250,863.11 ; v1(4175,1095) 4179.33,1099.33 U20.108@4250,1099.33 ; U20.91@4250,764.68 4309,764.68 v1(4319.11,774.8) ; U29.10@4347.8,305.91 v1@4510,305.91 ; v1(4510,305) v1@4510,305.91 ; v1@4510,310 v1@4510,305.91 ; v1@4514.09,305.91 U29.5@4572.2,305.91
  Top Layer w10: U7.3@741,1884.7 815.3,1884.7 v1(835,1865) ; U31.5@5507.58,189.75 5520.58,176.75 U31.2@5520.58,169.75 5520.58,130.92 C108.2@5546.5,105 ; U24.6@5514.21,700.2 5514.21,725.79 5481.01,758.99 5489.6,767.58 5489.6,784.38 5514.21,808.99 U24.7@5514.21,849.8
  Top Layer w12: J3.5@187.76,1920 227.94,1920 228.33,1920.39 ; v1(1100,275) 1115.75,290.75 U28.5@1152.8,290.75 U28.6@1152.8,265.16 ; v1(1100,595) 1110.75,605.75 U25.5@1152.8,605.75 U25.6@1152.8,580.16 ; v1(1100,955) 1112.2,967.2 U21.5@1152.8,967.2 ; v1(1100,1255) 1117.2,1272.2 U16.5@1152.8,1272.2 U16.6@1152.8,1246.61 ; U21.5@1152.8,965.6 1157.7,965.6 U21.6@1157.7,940 ; C89.1@1256.5,458.54 C89.1@1256.5,468.54 ; U22.8@2209.76,801.02 2248.98,801.02 2260,790 2260,726.5 C73.2@2223.5,690 ; U22.4@2209.76,903.39 2303.39,903.39 2330,930 2330,1017.99 C53.2@2287.99,1060 C43.2@2287.99,1130 ; C54.2@2360,1050 2356.2,1046.2 2356.2,927.07 2379.89,903.39 U22.17@2430.24,903.39 ; C54.2@2360,1060 C45.2@2360,1130 ; C72.2@2421.5,690 2386.93,724.57 2386.93,790 2397.95,801.02 U22.13@2430.24,801.02
  Top Layer w15: S3.3@2965.87,131.42 S3.4@3324.13,131.42 3397.91,131.42 C104.1@3405,138.5 3456.5,138.5 v1(3465,130) ; U33.4@3789.8,102.2 3855,102.2 ; v1(3905,180) 3870,180 3855,165 3855,102.2 ; C107.2@4263.5,150 4215.7,102.2 U33.5@3973.4,102.2 3855,102.2 ; v2(5425,235) 5438.5,248.5 C101.2@5438.5,280
  Top Layer w20: v1(70.71,1629.96) v1(70.71,1629.96) D3.1@107.52,1630 ; 228.33,1920.39 252.94,1945 252.94,1973.94 265.5,1986.5 R22.1@295,1986.5 v1(295,2043.54) ; U9.2@426.93,1773.46 C17.2@495,1773.46 ; C17.2@495,1771.5 C17.2@495,1773.46 ; v1(495,1817.05) C17.2@495,1773.46 ; v1(561.46,188.54) C105.1@618.5,188.54 ; v1(561.46,258.54) C102.1@618.5,258.54 ; v1(561.46,343.54) C97.1@618.5,343.54 ; v1(561.46,413.54) C94.1@618.5,413.54 ; v1(561.46,503.54) C85.1@618.5,503.54 ; v1(561.46,573.54) C81.1@618.5,573.54 ; v1(561.46,658.54) C75.1@618.5,658.54 ; v1(561.46,728.54) C68.1@618.5,728.54 ; v1(561.46,865) C61.1@618.5,865 ; v1(561.46,935) C59.1@618.5,935 ; v1(561.46,1020) C57.1@618.5,1020 ; v1(561.46,1090) C47.1@618.5,1090 ; v1(561.46,1170) C40.1@618.5,1170 ; v1(561.46,1240) C39.1@618.5,1240 ; v1(561.46,1325) C34.1@618.5,1325 ; v1(561.46,1395) C32.1@618.5,1395 ; D1.1@570,1978.31 v1(570,2035.36) ; C15.2@660,1738.5 653.19,1731.69 D2.1@570,1731.69 528.23,1773.46 C17.2@495,1773.46 ; v1(735,1580) C22.2@735,1628.5 ; v1(1070,1525) C19.2@1070,1582.91 1101.06,1582.91 1156.65,1638.5 C20.2@1175,1638.5 C21.1@1250,1638.5 ; C89.1@1246.5,458.54 v1(1246.5,512.05) ; C64.1@1246.5,773.54 v1(1246.5,827.05) ; C44.1@1246.5,1130 v1(1246.5,1183.5) ; C28.1@1256.5,1450 1390,1450 1406.5,1466.5 C27.2@1406.5,1505 1406.5,1586.5 1445,1625 U12.3@1445,1665 ; C100.1@1586.5,285 1687.09,285 C93.2@1695,292.91 v1(1782.09,292.91) ; R108.2@1586.5,720 v1(1586.5,766.5) ; C38.1@1586.5,1275 v1(1586.5,1226.5) 1600.08,1212.91 C33.2@1695,1212.91 ; R43.2@1586.5,1410 v1(1635,1410) ; v1(1600,910) 1586.5,923.5 C58.1@1586.5,975 1620,975 1637.91,992.91 C46.2@1695,992.91 C46.2@1720,992.91 ; v1(1605,540) 1586.5,558.5 C80.1@1586.5,590 1645,590 1662.09,572.91 C71.2@1695,572.91 ; v1(1799,571) 1886.5,483.5 J14.2@1886.5,353.5 v1(1806.5,353.5) ; v1(1803.5,666.5) R114.1@1850,666.5 ; v1(1826.69,717.69) Y1.4@1826.69,782.17 1826.69,794.31 1780,841 1780,1002 1908,1130 v1(1941,1130) v1(2150,1130) ; v1(1886.5,86.5) J14.2@1886.5,166.5 ; Y1.2@1913.31,927.83 1913.31,913.69 1948.66,878.34 v1(1948.66,855) R97.1@1996.38,855 ; v1(1915,555) R113.1@1915,603.5 ; C55.2@1980,1036.5 v1(1980,1087) ; C65.2@2056.5,745 2085.5,716 v1(2103,716) ; J14.2@2073.5,166.5 2075,165 v1(2075,85) ; R116.1@2120,608.5 v1(2120,560) ; v1(2153.5,353.5) J14.2@2073.5,353.5 2073.5,471.5 2120,518 v1(2120,560) ; v1(2170,694) 2170,571 2159,560 v1(2120,560) ; C73.2@2223.5,690 C77.2@2223.5,620 2223.5,571.5 v1(2225,570) ; v1(2247.99,1185) 2272.99,1185 2287.99,1170 C43.2@2287.99,1130 ; C45.2@2360,1130 2360,1170 2375,1185 v1(2400,1185) ; v1(2420,570) 2421.5,571.5 C76.2@2421.5,620 C72.2@2421.5,690 ; v1(2432.57,1860.93) J4.179@2515.49,1860.93 ; v1(2605,640) 2606.49,638.51 R110.2@2655,638.51 ; v1(2605,770) 2606.49,768.51 R100.2@2655,768.51 ; v1(2605,960) 2605,965 2608.5,961.5 R89.1@2655,961.5 ; v1(2605,1090) 2605,1095 2608.5,1091.5 R81.1@2655,1091.5 ; v1(2605,1220) 2606.5,1221.5 R75.1@2655,1221.5 ; v1(2606.49,508.51) R124.2@2655,508.51 ; J4.157@2861.94,1860.93 2861.94,1900.93 2876.94,1915.93 v1(2901.94,1915.93) ; v1(3206.32,1945.93) 3208.4,1943.84 J4.135@3208.4,1860.93 ; v1(4319.11,774.8) 4374.8,774.8 4405,805 C63.2@4448.5,805 C66.2@4448.5,740 ; v1(4320.87,1779.13) 4320,1780 4320,1775 4330,1775 4383.86,1828.86 J5.111@4383.86,1861.93 ; Y2.2@4412.17,150.81 Y2.2@4425.89,150.81 ; v1(4455,465) 4475,485 C86.1@4508.5,485 ; v1(4510,305) 4510,234.92 Y2.2@4425.89,150.81 ; C92.1@4518.5,420 C86.1@4518.5,485 C86.1@4518.5,485.32 ; v1(4604.33,1816.14) J5.97@4604.33,1861.93 ; C106.2@4716.5,150 4716.5,86.5 4694.19,64.19 Y2.4@4557.84,64.19 4515.81,64.19 4429.19,150.81 Y2.2@4425.89,150.81 ; C99.1@4716.5,285.32 C96.1@4716.5,355 ; v1(4824.8,1816.14) J5.83@4824.8,1861.93 ; D9.1@4935,112.52 4897.48,112.52 4870,140 U27.4@4870,254.68 4909.68,254.68 4975,320 v1(4975,345) ; v1@4973.5,345 R134.1@4973.5,470 ; v1(5080,410) 5108.5,438.5 C88.1@5108.5,470 C83.1@5108.5,535 ; v1(5108.27,1816.14) J5.65@5108.27,1861.93 ; C4.2@5130,2213.5 C5.2@5195,2213.5 5241.5,2213.5 v1(5255,2200) ; C51.2@5395,1052.09 v1(5395,1109) v1@5395,1110 ; C52.2@5510,1052.09 v1(5510,1114) v1@5510,1115 ; J5.47@5517.72,1861.93 5517.72,1827.28 5535,1810 5570,1810 5579.84,1800.16 5579.84,1780 5555,1780 5549.21,1774.21 J5.46@5549.21,1728.07 ; v1(5525,2070) U5.2@5525,2117.24 ; C108.2@5546.5,105 v1(5595,105) ; v1(5555,2295) 5556.5,2293.5 R2.2@5556.5,2250 ; v1@5579.84,1775 v1@5579.84,1779.13 ; v2(5605,60) 5626,81 D10.2@5692.52,81 ; J5.38@5675.2,1728.07 5675.2,1779.8 v1(5675,1780) 5706.69,1811.69 J5.35@5706.69,1861.93 ; v2(5685,1241) 5741,1185 D5.2@5742.52,1185 ; C9.1@5701.5,2040 5731.5,2070 U1.4@5805,2070 v1(5805,2025) ; v1(5805,2295) C1.1@5868.5,2295 ; v1(5856,1325) U17.2@5856,1372.24 ; v1(5885.13,1543.7) 5886.63,1542.21 R35.2@5886.63,1498.7 ; J5.22@5927.17,1728.07 5927.17,1779.8 v1(5926.97,1780) 5958.66,1811.69 J5.19@5958.66,1861.93 ; C35.1@6032.5,1295 6052.5,1315 U13.4@6136,1315 v1(6136,1280) ; v1(6045,855) U23.7@6045,939.49 ; J5.10@6116.14,1728.07 6116.14,1779.8 v1(6115.95,1780) 6147.64,1811.69 J5.7@6147.64,1861.93 ; v1(6136,1540) C25.1@6199.5,1540 ; v1(6215,2070) U6.2@6215,2117.24 ; v1(6245,2295) 6246.5,2293.5 R3.2@6246.5,2250 ; C10.1@6391.5,2040 6421.5,2070 U2.4@6495,2070 v1(6495,2025) ; v1(6415,230) 6427.5,217.5 U32.3@6427.5,147.5 ; v1(6495,2295) C2.1@6558.5,2295 ; v1(6546,1325) U18.2@6546,1372.24 ; v1(6576,1545) 6577.5,1543.5 R31.2@6577.5,1500 ; C36.1@6722.5,1295 6742.5,1315 U14.4@6826,1315 v1(6826,1280) ; v1(6727.76,1710) 6755,1710 U10.3@6775,1690 ; C14.2@6781.5,1865 v1(6781.5,1920) ; v1(6826,1540) C26.1@6889.5,1540 ; v1(6885,2075) U4.2@6885,2122.24 ; v1(6915,2295) 6916.5,2293.5 R4.2@6916.5,2250 ; C11.1@7061.5,2040 7091.5,2070 U3.4@7165,2070 v1(7165,2025) ; v1(7165,2295) C3.1@7228.5,2295 ; v1(7215.31,1690) U11.2@7215.31,1737.24 ; v1(7216,1325) U19.2@7216,1372.24 ; v1(7245.31,1910) 7246.81,1908.5 R25.2@7246.81,1865 ; v1(7246,1543.54) 7247.5,1542.05 R36.2@7247.5,1498.54 ; C23.1@7391.5,1655 7421.5,1685 U8.4@7495,1685 v1(7495,1640) ; C37.1@7392.5,1295 7412.5,1315 U15.4@7496,1315 v1(7496,1280) ; v1(7495,1910) C13.1@7558.5,1910 ; v1(7496,1543.54) C24.1@7559.5,1543.54
  Top Layer w25: v1@815,130 v1(815.59,130.59) ; v2(6240,1155) 6262.52,1177.52 D4.2@6262.52,1215
  Top Layer w30: C87.2@5552.09,455 5600,455 v1(5615,470) ; C79.2@5552.09,570 5564.09,558 5591,558 v1(5619,530) ; v1(5670,455) 5694.76,430.24 C91.2@5775,430.24 ; v1(5872,651) 5872,585 C78.2@5910.83,585 5910.83,606.83 5920,616 v1(5920,668) ; v1(6230,874) 6231,873 T1.9@6349.5,873 ; v1(6271,972) 6272,971 T1.10@6349.5,971
  Top Layer w40: C78.2@5903.74,577.91 C78.2@5910.83,585
  Top Layer w45: C70.2@5770,577.91 C78.2@5903.74,577.91
  Bottom Layer w12: v1(561.46,503.54) 728.54,503.54 745,520 782.64,520 D25.1@815.59,487.05 848.54,520 902.64,520 D24.1@935.59,487.05 935.59,481.22 D26.1@884.41,430.04 ; v1(561.46,1170) 725,1170 740,1185 786.38,1185 D15.1@816.3,1155.08 846.22,1185 906.38,1185 D14.1@936.3,1155.08 934.08,1155.08 887.07,1108.07 D16.1@885.12,1108.07 ; D21.1@764.41,746.5 764.41,753.11 v1(816.3,805) ; D22.1@884.41,745.04 884.41,754.41 v1(935,805) ; C157.1@3405,566.5 3467.99,503.5 C158.1@3470.47,503.5 ; C131.1@3858.5,1119.02 3921.5,1182.01 C126.1@3921.5,1185
  Bottom Layer w20: v1(561.46,413.54) 577.95,430.04 D27.1@764.41,430.04 ; v1(561.46,1090) 579.53,1108.07 D17.1@765.12,1108.07 ; D12.1@765.12,1413.07 v1(765.12,1470.12) ; D11.1@885.12,1413.07 v1(885.12,1470.12) ; v1(1100,275) 1145,275 1161.5,291.5 C172.1@1161.5,330 ; v1(1100,595) 1145,595 1161.5,611.5 C155.1@1161.5,645 ; v1(1100,955) 1145,955 1161.5,971.5 C136.1@1161.5,1005 ; v1(1100,1255) 1145,1255 1161.5,1271.5 C125.1@1161.5,1310 ; C119.1@2578.48,1727.07 2578.48,1773.48 v1(2580,1775) ; C178.2@2798.5,130 2798.5,160.51 v1(2816.5,178.5) ; C118.1@2924.94,1727.07 2924.94,1773.48 v1(2926.46,1775) ; v1(3140,500) 3151.29,511.29 C160.2@3215,511.29 3274.41,511.29 C162.2@3300,485.7 ; v1(3140,800) 3152.09,812.09 C144.2@3215,812.09 3274.41,812.09 C148.2@3300,786.5 ; C165.1@3405,348.5 3448.5,348.5 v1(3450,350) 3503.5,350 C173.1@3523.5,330 ; C157.1@3405,566.5 C152.1@3405,638.5 C151.1@3470,638.5 3501.5,638.5 v1(3515,625) ; C140.1@3405,836.5 3428.98,860.47 v1(3494.49,860.47) ; C133.1@3434.65,1101.34 3463.86,1101.34 v1(3484.8,1080.39) ; C129.1@3596.46,1185 3596.46,1143.54 v1(3645,1095) ; C171.1@3703.5,355 3703.5,377.72 v1(3724.29,398.5) ; C128.1@3728.5,1185 C132.1@3728.5,1119.02 3728.5,1076.5 v1(3730,1075) ; v1(3775,690) U36.2@3826,690 ; v1(3845.24,405) 3846.5,405 3853.5,398 3873,398 3896.5,374.5 C170.1@3896.5,355 ; C175.1@3856.5,200 3885,200 v1(3905,180) ; C124.2@3866.5,1315 3892.09,1340.59 C123.2@3892.09,1400 v1(3892.09,1457.91) ; C126.1@3921.5,1185 3921.5,1256.5 v1(3935,1270) ; v1(4085,405) 4066.5,386.5 C169.1@4066.5,355 R192.1@4138.5,355 ; v1(4145.91,489.09) 4170,465 C163.1@4198.5,465 ; v1(4175,885) 4175,860.32 C142.1@4198.82,836.5 C141.1@4265,836.5 4298.5,836.5 4319.11,815.89 v1(4319.11,774.8) ; v1(4175,1095) 4251.5,1095 C134.1@4265,1081.5 ; C154.1@4259.84,655 4330,655 v1(4375,610) ; v1@4320,1780 v1(4320.87,1779.13) C117.1@4320.87,1728.07 ; C147.2@4365,786.5 4390.59,812.09 C143.2@4450,812.09 4450,845 v1(4475,870) ; v1(4604.33,1816.14) 4630.31,1816.14 4667.32,1779.13 C116.1@4667.32,1728.07 ; v1(4740,795) U35.4@4740,865 ; R171.2@4793.5,1120.5 R171.4@4793.5,1085.5 R171.6@4793.5,1054.5 R171.8@4793.5,1019.5 4793.5,956.5 v1(4795,955) ; v1(4824.8,1816.14) 4843.86,1816.14 4865,1795 4865,1750.87 C115.1@4887.8,1728.07 ; v1(5255,2200) 5255,2150 5270,2135 U34.4@5325,2135 ; R173.1@5443.5,1010 5443.5,1088.5 v2(5450,1095) ; v3(5512.24,775) 5524.25,762.99 R180.1@5575,762.99 ; C127.1@5576.5,1185 R166.2@5576.5,1245 5625,1245 v2(5645,1265) ; v1@5579.84,1780 v1(5580.71,1779.13) C114.1@5580.71,1728.07 ; C112.1@5805,2231.5 v1@5805,2293.5 ; C153.2@5826.5,700 5880,700 v1(5905,725) ; R170.1@5960,1136.5 v1(5960,1205) ; C130.2@6041.38,1133.5 v1(6041.38,1198.62) ; C174.2@6122,269.5 v2(6122,319) ; C122.1@6136,1476.5 v1(6136,1540) ; C164.2@6305,461.5 6305,505 6303,507 v1(6305,507) ; R200.1@6395,176.5 6395,210 v1(6415,230) ; C111.1@6495,2232.99 v1(6495,2295) ; C121.1@6826,1476.5 v1(6826,1540) ; C110.1@7165,2232.99 v1(7165,2295) ; C113.1@7495,1841.5 v1(7495,1910) ; C120.1@7496,1480.04 v1(7496,1543.54)
  Bottom Layer w25: v1(815.59,130.59) D29.1@815.59,172.05 ; v1(816.3,805) D20.1@816.3,850.08 ; v1(935,130) 935.59,130.59 D28.1@935.59,172.05 ; v1@936.3,805 D19.1@936.3,850.08 ; R178.1@6013.5,939.49 6013.5,886.5 v1(6045,855) 6083.5,816.5 C150.2@6083.5,750 ; v1(6118.5,536.5) R184.1@6118.5,585
  Bottom Layer w30: C145.2@3811.5,805 3811.5,844.41 C138.2@3862.09,895 3862.09,942.09 v1(3880,960) ; C137.2@3811.5,985 3840,985 v1(3860,1005) ; C156.2@5525,570 5579,570 v1(5619,530) ; C168.2@5620,372.09 5647.09,372.09 5670,395 v1(5670,455) 5760,455 5775,440 C167.2@5775,372.09 C166.2@5925,372.09 ; R178.1@6013.5,939.49 6013.5,987.5
  Bottom Layer w40: D18.2@5868.74,1022 5979,1022 6013.5,987.5
  other v1: 5545,55 6390,60 6550,60 6195,65 4715,320 3075,370 3018,500 3070,500 3980,535 3980,580 6553,1115 6173.74,1155 6553,1160 1850,1405 1325,1451.46 245,1545 515,1550 7075,1700 1845,1720 1650,1725 7075,1745 800,1830 835,1830 870,1830 2290,1830 800,1865 870,1865 2240,1880 800,1900 835,1900 870,1900 1650,1905 1845,1910 435,1985 780,2125 2715,2135 2675,2215 515,2275 690,2275 1660,2280 1775,2280 1885,2280 2005,2280 2775,2305
  other v2: 6190,260 5370,1365 5370,1445 5445,1450
  other v3: 5465,735.63 5417.76,775 5465,775 5465,814.37
DOUTN_CH_U: J1.7 R45.1 | length 1103.8
  Top Layer w8: R45.1@3261.81,1403.62 3261.81,1426.02 3555,1719.21 3555,1915 3340,2130 3340,2222.01 J1.7@3287.01,2275
DOUTN_CH_V: J1.11 R49.1 | length 1012.7
  Top Layer w8: R49.1@3481.81,1403.62 3481.81,1426.81 3655,1600 3655,2015 3540,2130 3540,2222.01 J1.11@3487.01,2275
DOUTN_CH_W: J1.15 R53.1 | length 921.1
  Top Layer w8: J1.15@3687.01,2275 3740,2222.01 3740,2129.5 3754.4,2115.1 3754.4,1510 3701.81,1457.41 R53.1@3701.81,1403.62
DOUTN_U_PH: J1.20 R57.1 | length 799.9
  Top Layer w8: J1.20@3887.01,2175 3887.01,2132.01 3870,2115 3870,1525 3921.81,1473.19 R57.1@3921.81,1403.62
DOUTN_V_PH: J1.24 R61.1 | length 874.4
  Top Layer w8: J1.24@4087.01,2175 4087.01,2132.01 3990,2035 3990,1580 4141.81,1428.19 R61.1@4141.81,1403.62
DOUTN_VDC: J1.32 U20.45 | length 4843.2
  Top Layer w8: v1(3615,60) 3615,100 3647.64,132.64 U20.45@3647.64,339.49 ; J1.32@4487.01,2175 4562.21,2099.8 4933.09,2099.8 4960.89,2127.6 5220.37,2127.6 5265,2082.97 5265,1690 5235,1660 5235,90 v1(5265,60)
  Bottom Layer w8: v1(3615,60) 3631,44 5249,44 v1(5265,60)
DOUTN_W_PH: J1.28 R65.1 | length 952.3
  Top Layer w8: J1.28@4287.01,2175 4287.01,2132.01 4106,1951 4106,1684 4361.81,1428.19 R65.1@4361.81,1403.62
DOUTP_CH_U: J1.8 J5.107 R24.2 R44.1 | length 5093
  Top Layer w8: R44.1@3206.81,1403.62 3206.81,1426.81 3531,1751 3531,1889 3287.01,2132.99 J1.8@3287.01,2175 ; J5.107@4446.85,1861.93 v1(4446.85,1953.15) ; R24.2@7115,1866.5 v1(7115,1915)
  Bottom Layer w8: J1.8@3287.01,2175 3477.01,1985 4415,1985 v1(4446.85,1953.15) 4460,1940 5466.85,1940 5480,1953.15 7076.85,1953.15 v1(7115,1915)
DOUTP_CH_V: J1.12 J5.103 R14.2 R48.1 | length 4600.7
  Top Layer w8: R48.1@3426.81,1403.62 3426.81,1426.81 3630,1630 3630,1990 3487.01,2132.99 J1.12@3487.01,2175 ; v1(4490,2030) 4509.84,2010.16 J5.103@4509.84,1861.93 ; v1(6770,2030) 6780,2040 R14.2@6780,2083.5
  Bottom Layer w8: J1.12@3487.01,2175 3547.01,2115 3655,2115 3745,2025 4485,2025 v1(4490,2030) 4540,1980 5390,1980 5420.16,2010.16 5467.5,2010.16 5508.71,1968.95 6758.95,1968.95 6770,1980 v1(6770,2030)
DOUTP_CH_W: J1.16 J5.99 R13.2 R52.1 | length 3616.3
  Top Layer w8: R52.1@3646.81,1403.62 3646.81,1431.81 3730,1515 3730,2085 3687.01,2127.99 J1.16@3687.01,2175 ; J5.99@4572.83,1861.93 4572.83,1930 4605,1962.17 v1(4605,2010) ; v1(6090,2025) 6110,2045 R13.2@6110,2083.5
  Bottom Layer w8: J1.16@3687.01,2175 3687.01,2122.99 3762.8,2047.2 3884.54,2047.2 3897.34,2060 4555,2060 v1(4605,2010) 4619.2,1995.8 5379.84,1995.8 5410,2025.96 5474.04,2025.96 5515.25,1984.75 6049.75,1984.75 v1(6090,2025)
DOUTP_U_PH: J1.19 J5.108 R39.2 R56.1 | length 4351.8
  Top Layer w8: R56.1@3866.81,1403.62 3866.81,1428.19 3840,1455 v1(3840,1630) 3840,2227.99 J1.19@3887.01,2275 ; v1(4446.85,1630) J5.108@4446.85,1728.07 ; R39.2@7111,1496.5 v1(7111,1540)
  Bottom Layer w8: v1(3840,1630) v1(4446.85,1630) 7021,1630 v1(7111,1540)
DOUTP_V_PH: J1.23 J5.104 R37.2 R60.1 | length 3045.8
  Top Layer w8: R60.1@4086.81,1403.62 4086.81,1428 3960,1554.81 v1(3960,1565) 3960,2050 4040,2130 4040,2227.99 J1.23@4087.01,2275 ; J5.104@4509.84,1728.07 4509.84,1540.16 v1(4510,1540) ; R37.2@5751,1496.5 v1(5751,1565)
  Bottom Layer w8: v1(3960,1565) 3986.15,1538.85 4508.85,1538.85 v1(4510,1540) 4590,1540 4615,1565 v1(5751,1565)
DOUTP_VDC: J1.31 J5.76 R8.2 U20.46 | length 5547.2
  Top Layer w8: v1(3650,95) 3667.32,112.32 U20.46@3667.32,339.49 ; J1.31@4487.01,2275 4540,2222.01 4540,2150 4574.4,2115.6 4926.54,2115.6 4954.34,2143.4 5226.91,2143.4 5295,2075.31 v1(5295,2025) v1(5295,1710) 5295,1675 5265,1645 5265,124.9 v1(5295,94.9) ; J5.76@4950.79,1728.07 4950.79,1774.29 v1(4951.5,1775) ; v1(5420,2130) R8.2@5420,2183.5
  Bottom Layer w8: v1(3650,95) 3685.2,59.8 5209.8,59.8 5245,95 5294.9,95 v1(5295,94.9) ; v1(4951.5,1775) 5016.5,1710 v1(5295,1710) ; v1(5295,2025) 5350,2025 5420,2095 v1(5420,2130)
DOUTP_W_PH: J1.27 J5.100 R38.2 R64.1 | length 3567.2
  Top Layer w8: J1.27@4287.01,2275 4240,2227.99 4240,2135 4080,1975 4080,1654.81 v1(4139.81,1595) 4306.81,1428 R64.1@4306.81,1403.62 ; J5.100@4572.83,1728.07 4572.83,1597.17 v1(4575,1595) ; R38.2@6441,1496.5 v1(6441,1565)
  Bottom Layer w8: v1(4139.81,1595) v1(4575,1595) 6411,1595 v1(6441,1565)
EARTH: J3.6 J3.7 J3.8 J3.9 MH1.1 | length 901.2
  Top Layer w20: MH1.1@137.8,2224.41 76.85,2163.46 J3.7@76.85,2030.43 ; J3.9@195,1781.5 195,1725 179.57,1709.57 J3.8@76.85,1709.57 J3.7@76.85,2030.43 ; J3.6@195,1956.5 195,2010 174.57,2030.43 J3.7@76.85,2030.43
EEPROM_WP: R194.1 U20.40 U37.7 | length 1042.4
  Top Layer w8: v2(3510,125) 3527.66,125 3549.21,146.56 U20.40@3549.21,339.49
  Bottom Layer w8: U37.7@2940,235 2940,300 2948.58,308.58 3129.92,308.58 R194.1@3190,248.5 3190,150 3250,90 3475,90 v2(3510,125)
FPGA_DAC_ENABLE-3: U20.10 U25.15 | length 2521.7
  Top Layer w8: U25.15@1377.2,682.52 1417.52,682.52 1550,815 1610,815 1640,845 v2(1700,845) ; v2(2240,1240) 2261,1261 2951.97,1261 3240.37,972.6 3307.71,972.6 3358.15,922.16 U20.10@3419.29,922.16
  Bottom Layer w8: v2(1700,845) 1725,870 1725,1004.69 1985.31,1265 2215,1265 v2(2240,1240)
FPGA_DAC_ENABLE-4: U20.9 U28.15 | length 2862.1
  Top Layer w8: U28.15@1377.2,367.52 1417.52,367.52 1500,450 1735,450 v2(1755,470) ; v2(2180,1225) 2231.8,1276.8 2958.51,1276.8 3246.91,988.4 3314.26,988.4 3360.81,941.85 U20.9@3419.29,941.85
  Bottom Layer w8: v2(1755,470) 1765.8,480.8 1765.8,1000.8 1965,1200 2125.68,1200 2150.68,1225 v2(2180,1225)
FPGA_DAC_SCK: R179.1 U25.10 U28.10 | length 2571.1
  Top Layer w8: U28.10@1377.2,239.57 1333.03,239.57 1324.06,248.54 1324.06,544.06 1334.57,554.57 U25.10@1377.2,554.57 1425.43,554.57 1440,540 1440,515 1468.6,486.4 1656.4,486.4 1683,513 1767.4,513 v2(1841.2,439.2)
  Bottom Layer w8: v2(1841.2,439.2) 2821.54,439.2 3105.8,723.46 3105.8,870 3125.8,890 R179.1@3181.38,890
FPGA_DAC_SDI: R175.1 U25.11 U28.11 | length 2621.7
  Top Layer w8: U28.11@1377.2,265.16 1439.84,265.16 v1(1475,230) ; U25.11@1377.2,580.16 1439.84,580.16 v1(1465,555) 1517.8,502.2 1637.2,502.2 1665,530 1794,530 v2(1835,489)
  Bottom Layer w8: v1(1465,555) 1475,545 v1(1475,230) ; v2(1835,489) 1869,455 2810,455 3090,735 3090,910 3130,950 R175.1@3175,950
FPGA_DAC_SYNC: U20.7 U25.9 U28.9 | length 3247.5
  Top Layer w8: v1(1377.2,166.34) U28.9@1377.2,213.98 ; U25.9@1377.2,528.98 1377.2,481.34 1388.54,470 v1(1425,470) 1700,470 v2(1710,480) ; v2(2080,1235) 2170,1325 2238.4,1325 2255,1308.4 2971.6,1308.4 3260,1020 3330,1020 3368.78,981.22 U20.7@3419.29,981.22
  Bottom Layer w8: v1(1377.2,166.34) 1425,214.13 v1(1425,470) ; v2(1710,480) 1750,520 1750,1007.34 1977.66,1235 v2(2080,1235)
FPGA_LDAC: U20.8 U25.16 U28.16 | length 2846.7
  Top Layer w8: U28.16@1377.2,393.11 v2(1377.2,425) ; U25.16@1377.2,708.11 v2(1377.2,740) 1493,855.8 1610.8,855.8 1645,890 v2(1690,890) ; v2(2180,1292.6) 2965.06,1292.6 3253.46,1004.2 3320.8,1004.2 3363.46,961.54 U20.8@3419.29,961.54
  Bottom Layer w8: v2(1377.2,425) v2(1377.2,740) ; v2(1690,890) 1690,992.03 1990.57,1292.6 v2(2180,1292.6)
FPGA_SPI_CS#: R127.2 U20.38 U27.1 | length 1967.8
  Top Layer w8: v1(3465,245) 3465,250 3509.84,294.84 U20.38@3509.84,339.49 ; v1(4765,120) 4765,385 4784.68,404.68 U27.1@4870,404.68 4857.68,404.68 4854,401 4830,425 R127.2@4830,473.5
  Bottom Layer w8: v1(3465,245) 3495,275 3804,275 3837,242 3911,242 4016.2,136.8 4418.2,136.8 4435,120 v1(4765,120)
FPGA_SRAM_CS: R103.1 U20.81 U35.1 | length 661.5
  Top Layer w8: U20.81@4250,567.83 4322.17,567.83 v2(4325,565) ; v2(4570,795) 4591.5,816.5 R103.1@4640,816.5
  Bottom Layer w8: v2(4325,565) 4490,565 4550,625 4550,775 v2(4570,795) 4590,815 U35.1@4590,865
FPGA_SRAM_HOLD: R121.1 U20.80 U35.7 | length 620.6
  Top Layer w8: U20.80@4250,548.15 4296.85,548.15 v2(4315,530) ; v2(4630,590) 4661.5,558.5 R121.1@4735,558.5
  Bottom Layer w8: v2(4315,530) 4570,530 v2(4630,590) 4640,600 U35.7@4640,676
FPGA_SRAM_SCLK: R119.1 U35.6 | length 385.2
  Top Layer w8: R119.1@4403.62,655 4635,655 v2(4690,600)
  Bottom Layer w8: v2(4690,600) U35.6@4690,676
FPGA_SRAM_SDI: R185.1 U35.5 | length 438.8
  Bottom Layer w8: R185.1@4413.62,505 4575,505 4630,560 4695,560 4740,605 U35.5@4740,676
FPGA_SRAM_SDO: R174.2 U20.82 | length 794.6
  Top Layer w8: v2(4187.48,587.52) U20.82@4250,587.52
  Bottom Layer w8: v2(4187.48,587.52) 4199.96,600 4330,600 4347.8,582.2 4481.4,582.2 4525,625.8 4525,922.24 R174.2@4572.76,970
